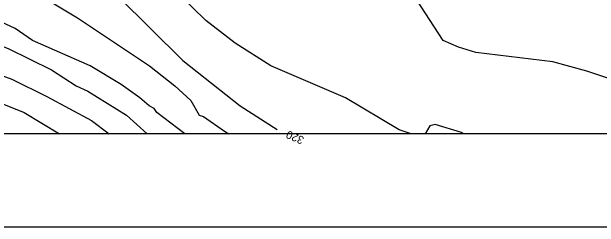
# Model space of a CAD drawing. Extents: x -510989 to -501240, y -1184665 to -1176089.
# Drawn here: x -502134.9 to -501694.8, y -1184460 to -1184298.4 of the extents above; entities that cross this region are included whole.
import ezdxf

# ---------------------------------------------------------------- set-up
doc = ezdxf.new("R2010")
doc.units = 0
for name, color, linetype in [('rozpiska', 7, 'Continuous'), ('vrstevnice_01', 7, 'Continuous'), ('vrstevnice_02', 7, 'Continuous'), ('vrstevnice_04', 7, 'Continuous')]:
    doc.layers.add(name, color=color, linetype=linetype)

msp = doc.modelspace()

# ---------------------------------------------------------------- linework, layer by layer
at = {"layer": 'rozpiska'}
for points in [[(-501240.19, -1178160), (-501240.19, -1184460), (-507180.19, -1184460), (-507180.19, -1178160)], [(-507110.19, -1184390), (-507110.19, -1178230), (-501310.19, -1178230), (-501310.19, -1184390)]]:
    msp.add_lwpolyline(points, close=True, dxfattribs=at)
at = {"layer": 'vrstevnice_01'}
for points in [[(-501661.81, -1184357), (-501704, -1184343), (-501729.59, -1184336), (-501787.31, -1184329), (-501800.31, -1184325), (-501811.81, -1184320), (-501838.09, -1184279), (-501850.31, -1184253), (-501898.31, -1184204), (-501921.59, -1184187), (-501934.09, -1184197), (-501966.69, -1184198), (-501985.81, -1184193), (-502002.41, -1184173), (-502001.81, -1184103), (-502013.19, -1184098), (-502032.59, -1184098), (-502048.09, -1184095), (-502054.19, -1184075), (-502053.41, -1184049), (-502078.91, -1184012), (-502146.81, -1183950)], [(-502391.41, -1184127), (-502385.09, -1184124), (-502359, -1184107), (-502342.69, -1184100), (-502327.19, -1184096), (-502311.81, -1184095), (-502287.5, -1184097), (-502274.09, -1184100), (-502258.41, -1184106), (-502235.81, -1184119), (-502222.41, -1184129), (-502172.59, -1184179), (-502148.5, -1184208), (-502134.69, -1184229), (-502124.19, -1184241), (-502121.19, -1184246), (-502121.81, -1184256), (-502079.69, -1184269), (-502054.91, -1184287), (-502006.59, -1184335), (-501963.69, -1184369), (-501935.97, -1184386.7)], [(-502005.31, -1184390), (-502026.09, -1184374), (-502028.09, -1184371), (-502031.91, -1184369), (-502038.81, -1184363), (-502052.81, -1184353), (-502076, -1184339), (-502119.31, -1184320), (-502132.31, -1184311), (-502160.5, -1184298), (-502204.69, -1184279), (-502240.41, -1184268), (-502267.19, -1184261), (-502318.91, -1184260), (-502323.59, -1184258), (-502324.69, -1184249), (-502365.59, -1184244), (-502386.91, -1184243)], [(-502409.31, -1184287), (-502367.41, -1184315), (-502346.19, -1184317), (-502318.81, -1184313), (-502290.69, -1184313), (-502242.31, -1184317), (-502218, -1184322), (-502170.5, -1184336), (-502134.91, -1184349), (-502108.59, -1184362), (-502075.19, -1184380), (-502061.98, -1184390)]]:
    msp.add_lwpolyline(points, dxfattribs=at)
at = {"layer": 'vrstevnice_02'}
for points in [[(-501835.7, -1184390), (-501844.59, -1184387), (-501884.81, -1184363), (-501940.91, -1184339), (-501967.5, -1184322), (-501989.41, -1184305), (-502009.69, -1184285), (-502023.09, -1184276), (-502025, -1184271), (-502024.41, -1184264), (-502033.31, -1184249), (-502084.81, -1184191), (-502093.41, -1184178), (-502119.59, -1184146), (-502154.81, -1184099), (-502189.31, -1184062), (-502206.09, -1184048), (-502223.59, -1184038), (-502226.41, -1184039), (-502336.91, -1183986)], [(-502388.41, -1184192), (-502376.91, -1184184), (-502351.31, -1184177), (-502340.91, -1184178), (-502315.81, -1184182), (-502289.81, -1184190), (-502252.81, -1184209), (-502209.91, -1184236), (-502207.81, -1184240), (-502208.09, -1184246), (-502206.5, -1184247), (-502161.09, -1184261), (-502120.09, -1184282), (-502085.5, -1184303), (-502031.59, -1184339), (-502012.69, -1184354), (-502000.69, -1184365), (-501994.41, -1184376), (-501991.31, -1184377), (-501975.59, -1184388), (-501972.16, -1184390)], [(-502405.41, -1184268), (-502371.59, -1184273), (-502305.59, -1184280), (-502277.69, -1184285), (-502233.59, -1184294), (-502160.81, -1184317), (-502137.5, -1184326), (-502105.09, -1184342), (-502086.59, -1184354), (-502077.81, -1184358), (-502049, -1184376), (-502033.43, -1184390)], [(-502393.31, -1184341), (-502378, -1184347), (-502314.59, -1184340), (-502278.5, -1184340), (-502247.69, -1184342), (-502196.59, -1184351), (-502155.41, -1184362), (-502125.59, -1184374), (-502099.19, -1184390)], [(-501796.25, -1184390), (-501797.91, -1184389), (-501817.81, -1184383), (-501821.81, -1184384), (-501825.15, -1184390)]]:
    msp.add_lwpolyline(points, dxfattribs=at)

# ---------------------------------------------------------------- texts
at = {"layer": 'vrstevnice_04'}
msp.add_text('320', height=6, rotation=156.7119, dxfattribs=at).set_placement((-501915.39, -1184392.56))

doc.saveas('drawing.dxf')
